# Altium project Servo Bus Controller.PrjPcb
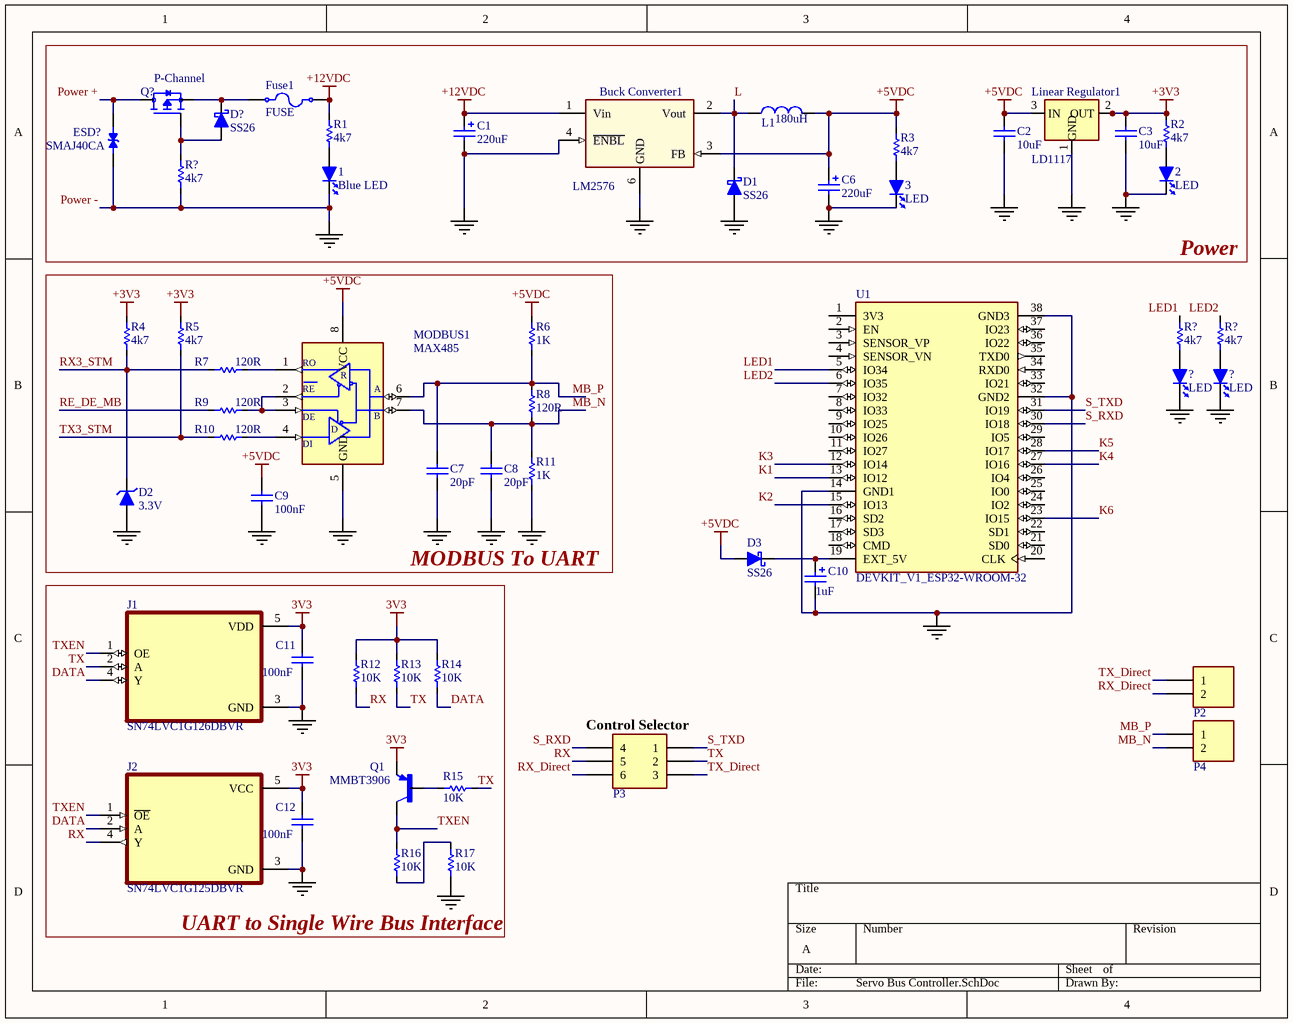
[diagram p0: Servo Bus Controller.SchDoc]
2 sheets, 98 parts. Net scope: global (net labels, ports and power ports of the same name join across sheets).
Sheets:
  Servo Bus Controller.SchDoc
  Actuators Control.SchDoc

## Sheet Servo Bus Controller.SchDoc
size A; SheetNumber: 1; SheetTotal: 2

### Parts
(Parts that share a designator on the sheet are numbered #1, #2 ... from top to bottom, then left to right.)
1  Blue LED  [LED0805]
2  LED  [LED1206]
3  LED  [LED1206]
?#1  LED  [LED1206]
?#2  LED  [LED1206]
Buck_Converter1  LM2576  [SOIC127P600X175-8N]
C1  220uF  [CAP AL-EL H12MM D8MM P3.5MM]
C2  10uF  [CC3216-1206L]
C3  10uF  [CC3216-1206L]
C6  220uF  [CAP AL-EL H12MM D8MM P3.5MM]
C7  20pF  [CC3216-1206L]
C8  20pF  [CC3216-1206L]
C9  100nF  [CC3216-1206L]
C10  1uF  [CAP AL-EL H12MM D8MM P3.5MM]
C11  100nF  [CC1608-0603L]
C12  100nF  [CC1608-0603L]
D1  SS26  [SMB]
D2  3.3V  [SOD123]
D3  SS26  [SMB]
D?#1  SS26  [SMB]
ESD?  SMAJ40CA  [DIOM4325X250N]
Fuse1  FUSE  [FUSE 5x20]
J1  SN74LVC1G126DBVR  [SOT95P280X145-5N]
J2  SN74LVC1G125DBVR  [SOT95P280X145-5N]
L1  180uH  [FPI1005]
Linear_Regulator1  LD1117  [SOT230P700X180-4N]
MODBUS1  MAX485  [SOIC127P600X175-8N]
P2  CONNECTOR, 1x2, 2P  [HDR_MALE_1X2_2P_2.54MM_180]  (value not drawn)
P3  CONNECTOR, 1x3, 3P  [HDR_FEMALE_2x3_3P_2.54mm_180]  (value not drawn)
P4  CONNECTOR, 1x2, 2P  [HDR_MALE_1X2_2P_2.54MM_180]  (value not drawn)
Q1  MMBT3906  [SOT95P260X140-3N]
Q?  P-Channel  [TO254P1052X465X1989-3]
R1  4k7  [CR3216-1206l]
R2  4k7  [CR3216-1206l]
R3  4k7  [CR3216-1206l]
R4  4k7  [CR3216-1206l]
R5  4k7  [CR3216-1206l]
R6  1K  [CR3216-1206l]
R7  120R  [CR3216-1206l]
R8  120R  [CR3216-1206l]
R9  120R  [CR3216-1206l]
R10  120R  [CR3216-1206l]
R11  1K  [CR3216-1206l]
R12  10K  [CR6332-2512L]
R13  10K  [CR6332-2512L]
R14  10K  [CR6332-2512L]
R15  10K  [CR6332-2512L]
R16  10K  [CR6332-2512L]
R17  10K  [CR6332-2512L]
R?#1  4k7  [CR3216-1206l]
R?#2  4k7  [CR3216-1206l]
R?#3  4k7  [CR3216-1206l]
U1  DEVKIT_V1_ESP32-WROOM-32  [MODULE_DEVKIT_V1_ESP32-WROOM-32]

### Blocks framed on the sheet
Power: 1-3 Buck_Converter1 C1-C3 C6 D1 D?#1 ESD? Fuse1 L1 Linear_Regulator1 Q? R1-R3 R?#1
MODBUS To UART: C7-C9 D2 MODBUS1 R4-R11

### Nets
3V3: C11.1 C12.1 J1.5(VDD) J2.5(VCC) Q1.2(E) R12.2 R13.2 R14.2
+3V3: C3.1 Linear_Regulator1.2(OUT) Linear_Regulator1.4(OUT) R2.2 R4.2 R5.2
+5VDC: Buck_Converter1.3(FB) C2.1 C6.1 C9.1 D3.1 L1.2 Linear_Regulator1.3(IN) MODBUS1.8(VCC) R3.2 R6.1
+12VDC: Buck_Converter1.1(Vin) C1.1 Fuse1.2 R1.2  [project net COM1]
Power -: 1.2(CATHODE) 2.2(CATHODE) 3.2(CATHODE) ?#1.2(CATHODE) ?#2.2(CATHODE) Buck_Converter1.4(~{ENBL}) Buck_Converter1.6(GND) C1.2 C2.2 C3.2 C6.2 C7.2 C8.2 C9.2 C10.2 C11.2 C12.2 D1.1 D2.1 ESD?.1 J1.3(GND) J2.3(GND) Linear_Regulator1.1(GND) MODBUS1.5(GND) R11.2 R17.2 R?#1.2 U1.14(GND1) U1.32(GND2) U1.38(GND3)  [also labelled GND]
DATA: J1.4(Y) J2.2(A) R14.1
K1: U1.13(IO12)
K2: U1.15(IO13)
K3: U1.12(IO14)
K4: U1.27(IO16)
K5: U1.28(IO17)
K6: U1.23(IO15)
L: Buck_Converter1.2(Vout) D1.2 L1.1
LED1: R?#2.2 U1.5(IO34)
LED2: R?#3.2 U1.6(IO35)
MB_N: C8.1 MODBUS1.7(B) P4.2 R8.2 R11.1
MB_P: C7.1 MODBUS1.6(A) P4.1 R6.2 R8.1
Power +: ESD?.2 Q?.2(D)
RE_DE_MB: R9.2
RX: J2.4(Y) P3.5 R12.1
RX3_STM: D2.2 R4.1 R7.2
RX_Direct: P2.2 P3.6
S_RXD: P3.4 U1.30(IO18)
S_TXD: P3.1 U1.31(IO19)
TX: J1.2(A) P3.2 R13.1 R15.1
TX3_STM: R5.1 R10.2
TX_Direct: P2.1 P3.3
TXEN: J1.1(OE) J2.1(~{OE}) Q1.3(C) R16.1
Net1_1: 1.1(ANODE) R1.1
Net2_1: 2.1(ANODE) R2.1
Net3_1: 3.1(ANODE) R3.1
Net?#1_1: ?#1.1(ANODE) R?#2.1
Net?#2_1: ?#2.1(ANODE) R?#3.1
NetC10_1: C10.1 D3.2 U1.19(EXT_5V)
NetD?#1_1: D?#1.1 Q?.1(G) R?#1.1
NetD?#1_2: D?#1.2 Fuse1.1 Q?.3(S)
NetMODBUS1_1: MODBUS1.1(RO) R7.1
NetMODBUS1_2: MODBUS1.2(~{RE}) MODBUS1.3(DE) R9.1
NetMODBUS1_4: MODBUS1.4(DI) R10.1
NetQ1_1: Q1.1(B) R15.2
NetR16_2: R16.2 R17.1

Not connected (* = marked no-connect by the designer): Buck_Converter1 5(NC) 7(NC) 8(NC); U1 1(3V3) 2(EN) 3(SENSOR_VP) 4(SENSOR_VN) 7(IO32) 8(IO33) 9(IO25) 10(IO26) 11(IO27) 16(SD2) 17(SD3) 18(CMD) 20(CLK) 21(SD0) 22(SD1) 24(IO2) 25(IO0) 26(IO4) 29(IO5) 33(IO21) 34(RXD0) 35(TXD0) 36(IO22) 37(IO23)

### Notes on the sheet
- (near P3) Control Selector
- UART to Single Wire Bus Interface

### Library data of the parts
1 = LED: Ozdisan: HL-PSC-2012H203BC
2 3 ?#1 ?#2 = LED: Ozdisan: HL-PC-3216U51GC
Buck_Converter1 = LM2576DP: 3A, 52kHz, Step-Down Switching Regulator
C1 C6 C10 = CAPACITOR POL: Capacitor; Ozdisan: PKRM-025V221MF115-T/A5.0
C2 C3 = CAPACITOR NON-POL: Capacitor; Ozdisan: CL31B106KAHNNNE
C7 C8 = CAPACITOR NON-POL: Capacitor; Ozdisan: CL31C220JBCNNNC
C9 = CAPACITOR NON-POL: Capacitor; Ozdisan: CL31B104KCFNNNE
C11 C12 = CAPACITOR NON-POL: Capacitor
D1 D3 D?#1 = DIODE SCHOTTKY: SINGLE SCHOTTKY DIODE / Check the suitability of the case with the pin number; Ozdisan: SS26-SMB-JQ
D2 = DIODE ZENER: Ozdisan: MMSZ3V3-HT
ESD? = SMAJ40CA: MP: SMAJ40CA-HT
Fuse1 = FUSE: Ozdisan: L-KLS5-2611
J1 = SN74LVC1G126DBVR: Single 1.65-V to 5.5-V buffer with 3-state outputs; MF: Texas Instruments
J2 = SN74LVC1G125DBVR: Single 1.65-V to 5.5-V buffer with 3-state outputs; MF: Texas Instruments
L1 = INDUCTOR: Ozdisan: FP11005-181M
Linear_Regulator1 = LM1117: Linear Voltage Regulators; Ozdisan: LD1117AS33TR
MODBUS1 = MAX485: ROHS-ICMAX485CSA MAXIM; Ozdisan: SN65HVD485EDR
P3 = CONNECTOR, 2x3, 3P
Q1 = MMBT3906: Trans GP BJT PNP 40V 3-Pin SOT-23; MF: Rectron
Q? = IRF9540: P-Channel 100 V 19A (Tc) 3.7W (Ta), 150W (Tc) Surface Mount DÂ²PAK (TO-263); MF: Vishay
R1-R5 R?#1-R?#3 = RESISTOR: Ozdisan: RC1206JR-074K7L
R6 R11 = RESISTOR: Ozdisan: 1206S4F1001T5E
R7-R10 = RESISTOR: Ozdisan: RC1206JR-07120RL
R12-R17 = RESISTOR
U1 = DEVKIT_V1_ESP32-WROOM-32: WROOM-32 Development Board ESP32 ESP-32S WiFi Bluetooth Dev Module; MF: Espressif Systems; MP: DEVKIT V1 ESP32-WROOM-32

## Sheet Actuators Control.SchDoc
size A; SheetNumber: 2; SheetTotal: 2
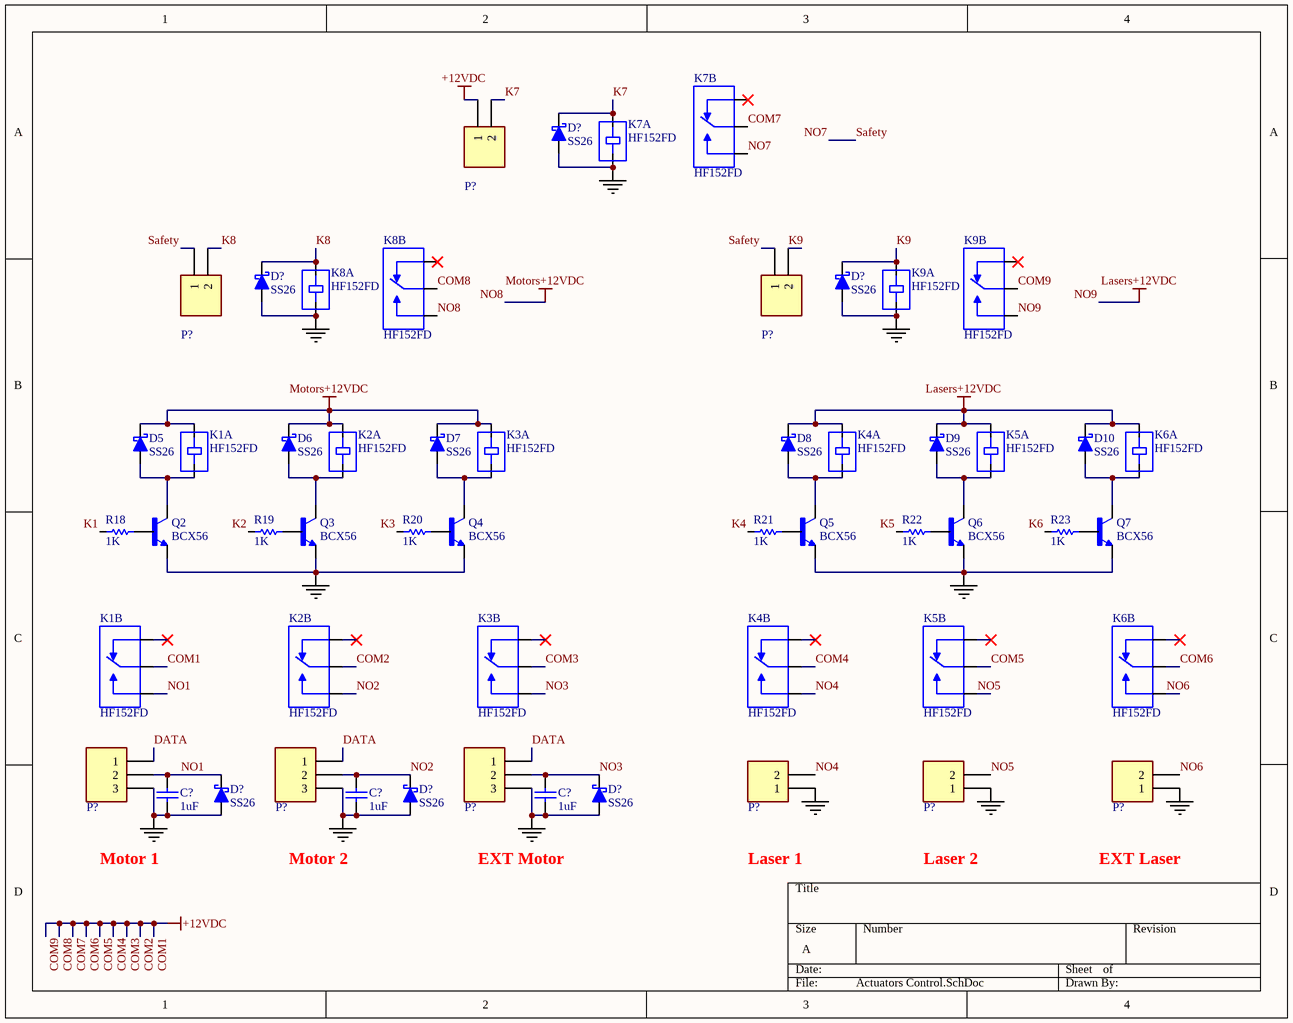
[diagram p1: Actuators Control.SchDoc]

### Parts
(Parts that share a designator on the sheet are numbered #1, #2 ... from top to bottom, then left to right.)
C?#1  1uF  [CC3216-1206L]
C?#2  1uF  [CC3216-1206L]
C?#3  1uF  [CC3216-1206L]
D5  SS26  [SMB]
D6  SS26  [SMB]
D7  SS26  [SMB]
D8  SS26  [SMB]
D9  SS26  [SMB]
D10  SS26  [SMB]
D?#2  SS26  [SMB]
D?#3  SS26  [SMB]
D?#4  SS26  [SMB]
D?#5  SS26  [SMB]
D?#6  SS26  [SMB]
D?#7  SS26  [SMB]
K1  HF152FD  [RELAY_HF152FD/012-1HS]  (parts A,B of 2)
K2  HF152FD  [RELAY_HF152FD/012-1HS]  (parts A,B of 2)
K3  HF152FD  [RELAY_HF152FD/012-1HS]  (parts A,B of 2)
K4  HF152FD  [RELAY_HF152FD/012-1HS]  (parts A,B of 2)
K5  HF152FD  [RELAY_HF152FD/012-1HS]  (parts A,B of 2)
K6  HF152FD  [RELAY_HF152FD/012-1HS]  (parts A,B of 2)
K7  HF152FD  [RELAY_HF152FD/012-1HS]  (parts A,B of 2)
K8  HF152FD  [RELAY_HF152FD/012-1HS]  (parts A,B of 2)
K9  HF152FD  [RELAY_HF152FD/012-1HS]  (parts A,B of 2)
P?#1  CONNECTOR, 1x2, 2P  [HDR_MALE_1X2_2P_2.54MM_180]  (value not drawn)
P?#2  CONNECTOR, 1x2, 2P  [HDR_MALE_1X2_2P_2.54MM_180]  (value not drawn)
P?#3  CONNECTOR, 1x2, 2P  [HDR_MALE_1X2_2P_2.54MM_180]  (value not drawn)
P?#4  CONNECTOR, 1x3, 3P  (value not drawn)
P?#5  CONNECTOR, 1x3, 3P  (value not drawn)
P?#6  CONNECTOR, 1x3, 3P  (value not drawn)
P?#7  CONNECTOR, 1x2, 2P  [HDR_MALE_1X2_2P_2.54MM_180]  (value not drawn)
P?#8  CONNECTOR, 1x2, 2P  [HDR_MALE_1X2_2P_2.54MM_180]  (value not drawn)
P?#9  CONNECTOR, 1x2, 2P  [HDR_MALE_1X2_2P_2.54MM_180]  (value not drawn)
Q2  BCX56  [SOT89R_INFINEON]
Q3  BCX56  [SOT89R_INFINEON]
Q4  BCX56  [SOT89R_INFINEON]
Q5  BCX56  [SOT89R_INFINEON]
Q6  BCX56  [SOT89R_INFINEON]
Q7  BCX56  [SOT89R_INFINEON]
R18  1K  [CR3216-1206l]
R19  1K  [CR3216-1206l]
R20  1K  [CR3216-1206l]
R21  1K  [CR3216-1206l]
R22  1K  [CR3216-1206l]
R23  1K  [CR3216-1206l]

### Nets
COM1: K1.3(COM) K2.3(COM) K3.3(COM) K4.3(COM) K5.3(COM) K6.3(COM) K7.3(COM) K8.3(COM) K9.3(COM) P?#1.1  [also labelled +12VDC, COM2, COM3, COM4, COM5, COM6, COM7, COM8, COM9]
GND: C?#1.2 C?#2.2 C?#3.2 D?#2.1 D?#3.1 D?#4.1 D?#5.1 D?#6.1 D?#7.1 K7.1(COIL2) K8.1(COIL2) K9.1(COIL2) P?#4.3 P?#5.3 P?#6.3 P?#7.1 P?#8.1 P?#9.1 Q2.3(E) Q3.3(E) Q4.3(E) Q5.3(E) Q6.3(E) Q7.3(E)  [project net Power -]
NO8: D5.2 D6.2 D7.2 K1.2(COIL1) K2.2(COIL1) K3.2(COIL1) K8.4(NO)  [also labelled Motors+12VDC]
NO9: D8.2 D9.2 D10.2 K4.2(COIL1) K5.2(COIL1) K6.2(COIL1) K9.4(NO)  [also labelled Lasers+12VDC]
DATA: P?#4.1 P?#5.1 P?#6.1
K1: R18.2
K2: R19.2
K3: R20.2
K4: R21.2
K5: R22.2
K6: R23.2
K7: D?#2.2 K7.2(COIL1) P?#1.2
K8: D?#3.2 K8.2(COIL1) P?#2.2
K9: D?#4.2 K9.2(COIL1) P?#3.2
NO1: C?#1.1 D?#5.2 K1.4(NO) P?#4.2
NO2: C?#2.1 D?#6.2 K2.4(NO) P?#5.2
NO3: C?#3.1 D?#7.2 K3.4(NO) P?#6.2
NO4: K4.4(NO) P?#7.2
NO5: K5.4(NO) P?#8.2
NO6: K6.4(NO) P?#9.2
NO7: K7.4(NO) P?#2.1 P?#3.1  [also labelled Safety]
NetD5_1: D5.1 K1.1(COIL2) Q2.2(C)
NetD6_1: D6.1 K2.1(COIL2) Q3.2(C)
NetD7_1: D7.1 K3.1(COIL2) Q4.2(C)
NetD8_1: D8.1 K4.1(COIL2) Q5.2(C)
NetD9_1: D9.1 K5.1(COIL2) Q6.2(C)
NetD10_1: D10.1 K6.1(COIL2) Q7.2(C)
NetQ2_1: Q2.1(B) R18.1
NetQ3_1: Q3.1(B) R19.1
NetQ4_1: Q4.1(B) R20.1
NetQ5_1: Q5.1(B) R21.1
NetQ6_1: Q6.1(B) R22.1
NetQ7_1: Q7.1(B) R23.1

Not connected (* = marked no-connect by the designer): K1 5(NC)*; K2 5(NC)*; K3 5(NC)*; K4 5(NC)*; K5 5(NC)*; K6 5(NC)*; K7 5(NC)*; K8 5(NC)*; K9 5(NC)*

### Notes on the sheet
- Motor 1
- Motor 2
- EXT Motor
- Laser 1
- Laser 2
- EXT Laser

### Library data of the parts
C?#1-C?#3 = CAPACITOR NON-POL: Capacitor; Ozdisan: CL31B104KCFNNNE
D5-D10 D?#2-D?#7 = DIODE SCHOTTKY: as D1 on sheet Servo Bus Controller
K1-K9 = Relay-HF152FD/012
Q2-Q7 = BCX56: BCX56-16,115 Bipolar (BJT) Transistor NPN 80 V 1 A 180MHz 1.25 W Surface Mount SOT-89; MF: Nexperia USA
R18-R23 = RESISTOR: Ozdisan: RC1206JR-074K7L

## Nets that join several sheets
COM1: Servo Bus Controller (Buck_Converter1.1 C1.1 Fuse1.2 R1.2), Actuators Control (10 pins)
Power -: Servo Bus Controller (30 pins), Actuators Control (24 pins)
DATA: Servo Bus Controller (J1.4 J2.2 R14.1), Actuators Control (P?#4.1 P?#5.1 P?#6.1)
K1: Servo Bus Controller (U1.13), Actuators Control (R18.2)
K2: Servo Bus Controller (U1.15), Actuators Control (R19.2)
K3: Servo Bus Controller (U1.12), Actuators Control (R20.2)
K4: Servo Bus Controller (U1.27), Actuators Control (R21.2)
K5: Servo Bus Controller (U1.28), Actuators Control (R22.2)
K6: Servo Bus Controller (U1.23), Actuators Control (R23.2)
